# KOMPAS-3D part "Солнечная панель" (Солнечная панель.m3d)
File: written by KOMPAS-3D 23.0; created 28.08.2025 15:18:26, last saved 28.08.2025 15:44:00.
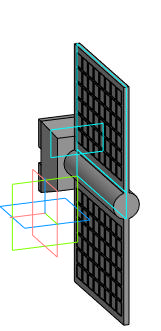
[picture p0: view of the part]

Document properties: Автор: Inspektor_Kot; Полное имя файла: I:\Autodesk Inventor Projects\ИМ-ИТ ЦД\Вариант 2\Солнечная панель.m3d

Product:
- Part/product: Солнечная панель

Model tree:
1. Эскиз:1  (with: Элемент выдавливания:2, Элемент выдавливания:3)  (labels: I:\Autodesk Inventor Projects\ИМ-ИТ ЦД\Вариант 2\Спутник.a3d)
2. Элемент выдавливания:1
     Расстояние 1 = 5
3. Смещенная плоскость:1  (with: Элемент выдавливания:1)
     Расстояние = 20
4. Эскиз:2  (with: Элемент выдавливания:1, Элемент выдавливания:3)  (labels: I:\Autodesk Inventor Projects\ИМ-ИТ ЦД\Вариант 2\Спутник.a3d)
5. Эскиз:3  (with: Элемент выдавливания:1)
6. Элемент по сечениям:1
7. Эскиз:4  (with: Элемент по сечениям:1)
8. Элемент выдавливания:2
     Расстояние 1 = 100
9. Нормальная плоскость:1  (with: Элемент выдавливания:2, Элемент выдавливания:1)
10. Эскиз:6  (with: Элемент выдавливания:2, Элемент по сечениям:1)
11. Элемент выдавливания:3
     Расстояние 1 = 4
12. Элемент выдавливания:4  (with: Элемент выдавливания:3)
     Расстояние 1 = 37
13. Эскиз:7  (with: Элемент выдавливания:3)
14. Элемент выдавливания:5
     Расстояние 2 = 0.5
15. Массив по сетке:1  (with: Элемент выдавливания:5, Эскиз:7, Элемент выдавливания:3)  (48 pattern instances)
     Шаг 1 = 11.5; Угол раствора = 90; Шаг 2 = 11.5
16. Средняя плоскость:1  (with: Элемент выдавливания:3)
17. Зеркальный массив:1
18. Экземпляр ( 1 )
19. Экземпляр ( 2 )  (with: Массив по сетке:1, Экземпляр ( 1 ), Элемент выдавливания:5)
20. Экземпляр ( 3 )  (with: Элемент выдавливания:5)
21. Экземпляр ( 4 )  (with: Элемент выдавливания:5)
22. Экземпляр ( 5 )  (with: Элемент выдавливания:5)
23. Экземпляр ( 6 )  (with: Элемент выдавливания:5)
24. Массив по концентрической сетке:1  (with: Элемент выдавливания:4, Зеркальный массив:1, Массив по сетке:1, Элемент выдавливания:5, Элемент выдавливания:3, Нормальная плоскость:1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)  (100 pattern instances)
     Шаг 2 = 360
